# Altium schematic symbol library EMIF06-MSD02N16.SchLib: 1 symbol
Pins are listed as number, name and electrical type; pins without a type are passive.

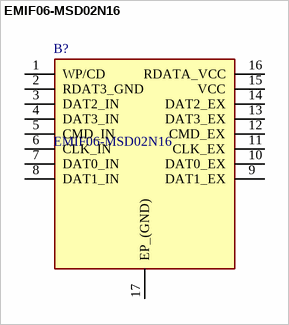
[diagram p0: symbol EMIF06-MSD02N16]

## EMIF06-MSD02N16
designator B?
6-Line EMI filter&ESD for SD card uQFN16 STMicroelectronics EMIF06-MSD02N16, EMI Filter & ESD Protector; Geometry.Height: 0mm
footprint EMIF06MSD02N16
pins: 1 WP/CD, 2 RDAT3_GND, 3 DAT2_IN, 4 DAT3_IN, 5 CMD_IN, 6 CLK_IN, 7 DAT0_IN, 8 DAT1_IN, 9 DAT1_EX, 10 DAT0_EX, 11 CLK_EX, 12 CMD_EX, 13 DAT3_EX, 14 DAT2_EX, 15 VCC, 16 RDATA_VCC, 17 EP_(GND)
